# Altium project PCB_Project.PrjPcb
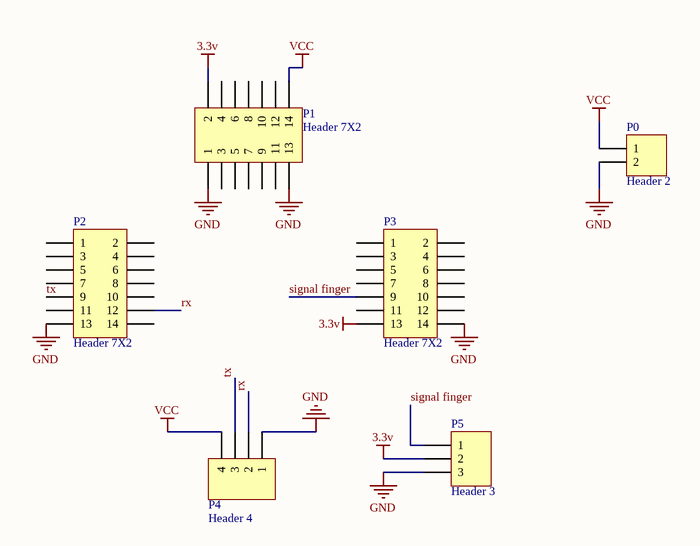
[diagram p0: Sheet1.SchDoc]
1 sheet, 6 parts. Net scope: global (net labels, ports and power ports of the same name join across sheets).
Board file: PCB1.PcbDoc

## Sheet Sheet1.SchDoc
size A; SheetNumber: 1; SheetTotal: 1

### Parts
P0  Header 2  [HDR1X2]
P1  Header 7X2  [HDR2X7]
P2  Header 7X2  [HDR2X7]
P3  Header 7X2  [HDR2X7]
P4  Header 4  [HDR1X4]
P5  Header 3  [HDR1X3]

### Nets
3.3v: P1.2 P3.13 P5.2
GND: P0.2 P1.1 P1.13 P2.13 P3.14 P4.1 P5.3
VCC: P0.1 P1.14 P4.4
rx: P2.12 P4.2
signal finger: P3.9 P5.1
tx: P2.9 P4.3

Not connected (* = marked no-connect by the designer): P1 3 4 5 6 7 8 9 10 11 12; P2 1 2 3 4 5 6 7 8 10 11 14; P3 1 2 3 4 5 6 7 8 10 11 12

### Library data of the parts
P0 = Header 2: Header, 2-Pin
P1-P3 = Header 7X2: Header, 7-Pin, Dual row
P4 = Header 4: Header, 4-Pin
P5 = Header 3: Header, 3-Pin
